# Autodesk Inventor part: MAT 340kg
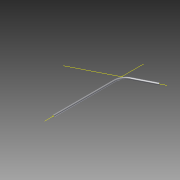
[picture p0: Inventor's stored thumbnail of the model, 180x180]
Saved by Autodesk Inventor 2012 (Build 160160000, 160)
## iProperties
Created: 2016-01
Part Number: MAT 340kg
Material: Default
Document SubType Name: Modeling
Designer: wmfoihay
Density: 1 g/cm^3
Author: wmfoihay
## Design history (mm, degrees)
sketch "Esquisse1"
  geometry: L1 (0, 0)-(0, 1950); L2 (205.57, 2284.542)-(800.805, 2586); A1 r 375 centre (375, 1950) between (205.57, 2284.542) and (0, 1950); 1 further point
  constraints: 4 end point, 2 point on circle, 2 point on line, 2 tangent, 1 centre point, 1 vertical
  dimensions: "d24" = 2586 vertical distance of L1.start L2.end (= Mat_Hauteur2); "d26" = 375 radius of A1; "d27" = 1950 distance of L1.start L1.end (= Mat_Haueur1); "d28" = 116.86 deg angle of L2 L1 (= Mat_Inclinaison)
node "Plan de construction2"
sketch "Esquisse3"
  geometry: C1 r 30.15 at (0, 0); 1 further point
  constraints: 1 centre point, 1 coincident
  dimensions: "d29" = 60.3 diameter of C1 (= Mat_Diam)
feature "Balayage2" sketch "Esquisse3" dims "d30" = 0
node "Axe de construction1"
node "Axe de construction2"
node "Solide2"
other parameters: "Mat_Haueur1" = 1950 [user parameter; used in 1 equation term], "Mat_Hauteur2" = 2586 [user parameter; used in 1 equation term], "Mat_Inclinaison" = 116.86 deg [user parameter; used in 1 equation term], "Mat_Diam" = 60.3 [user parameter; used in 1 equation term]
